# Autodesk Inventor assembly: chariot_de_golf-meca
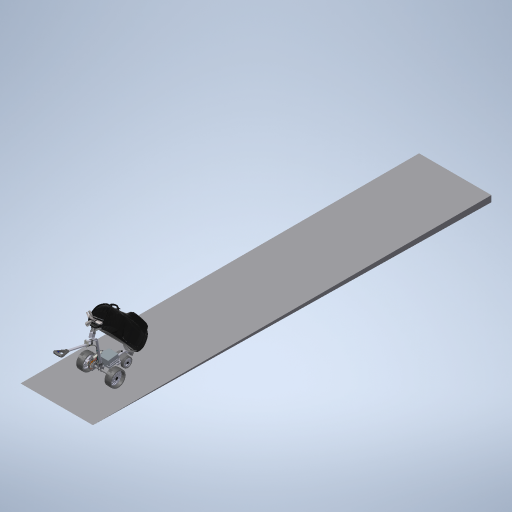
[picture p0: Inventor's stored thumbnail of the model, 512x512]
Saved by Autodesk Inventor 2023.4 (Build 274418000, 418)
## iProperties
Created: 2011-01
Part Number: chariot_de_golf-meca
Document SubType Name: Assembly
Designer: eric
Norme de conversion: STEP AP214IS
Nom du fichier: chariot_de_golf.STEP
Préprocesseur: SolidWorks 2007
Postprocesseur: Build: 342, Release: 2008 SP3 - Date: Tue 05/27/2008
Unités envoyées: MILLIMETERS
Incertitude: 1e-05
Author: eric
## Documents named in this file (6)
- C:\Users\bruno\Documents\1-Cours-2024-25\TSsI\7-Dynamique\chariot de golf\chariot_de_golf\chariot_de_golf_trolem\chariot_de_golf-meca.iam
- C:\Users\bruno\Documents\1-Cours-2024-25\TSsI\7-Dynamique\chariot de golf\chariot_de_golf\chariot_de_golf_trolem\Chassis.iam
- C:\Users\bruno\Documents\1-Cours-2024-25\TSsI\7-Dynamique\chariot de golf\chariot_de_golf\chariot_de_golf_trolem\essieu_avant.iam
- C:\Users\bruno\Documents\1-Cours-2024-25\TSsI\7-Dynamique\chariot de golf\chariot_de_golf\chariot_de_golf_trolem\essieu_arriere.iam
- C:\Users\bruno\Documents\1-Cours-2024-25\TSsI\7-Dynamique\chariot de golf\chariot_de_golf\chariot_de_golf_trolem\rotor moteur.iam
- C:\Users\bruno\Documents\1-Cours-2024-25\TSsI\7-Dynamique\chariot de golf\chariot_de_golf\chariot_de_golf_trolem\Sol-2.ipt
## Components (5 placed, 5 different names)
1. Chassis:1 [sub-assembly] — Logement:1, Logement:2, pilotage du moteur, Logement:3, Affleurement:2, Placage:1
2. essieu_avant:1 [sub-assembly] — Tangente:1, Logement:3, Tangente:3, Affleurement:3, Placage:1
3. essieu_arriere:1 [sub-assembly] — Logement:2, Tangente:2
4. rotor moteur:1 [sub-assembly] — Logement:1, pilotage du moteur
5. Sol-2:1 — Affleurement:1, Tangente:1, Tangente:2, Affleurement:2, Tangente:3, Affleurement:3
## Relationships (11: Insert 3, Flush 3, Tangent 3, Angle 1, Mate 1)
- Logement:1 [Insert]: Chassis:1 ↔ rotor moteur:1
- Logement:2 [Insert]: Chassis:1 ↔ essieu_arriere:1
- pilotage du moteur [Angle]: Chassis:1 ↔ rotor moteur:1
- Affleurement:1 [Flush]: Sol-2:1
- Tangente:1: essieu_avant:1 ↔ Sol-2:1
- Logement:3 [Insert]: Chassis:1 ↔ essieu_avant:1
- Tangente:2: essieu_arriere:1 ↔ Sol-2:1
- Affleurement:2 [Flush]: Chassis:1 ↔ Sol-2:1
- Tangente:3: essieu_avant:1 ↔ Sol-2:1
- Affleurement:3 [Flush]: essieu_avant:1 ↔ Sol-2:1
- Placage:1 [Mate]: Chassis:1 ↔ essieu_avant:1
